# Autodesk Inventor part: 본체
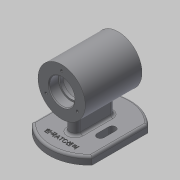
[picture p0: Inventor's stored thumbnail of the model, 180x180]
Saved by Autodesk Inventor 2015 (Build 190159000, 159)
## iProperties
Created: 2022-02
Part Number: 본체
Material: 일반
Document SubType Name: Modeling
Designer: 학생용
Density: 1 g/cm^3
Appearance: 기본값
Author: 학생용
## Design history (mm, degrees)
sketch "스케치1"
  geometry: C1 r 30 at (0, 0); 1 further point
  constraints: 1 centre point, 1 coincident
  dimensions: "d0" = 60 diameter of C1
extrude "돌출1" new body sketch "스케치1" distance "d1" = 72; taper "d2" = 0 deg
sketch "스케치2"
  geometry: C1 r 16 at (0, 0); 1 further point
  constraints: 1 centre point, 1 coincident
  dimensions: "d3" = 32 diameter of C1
extrude "돌출2" cut sketch "스케치2" distance "d4" = 12; taper "d5" = 0 deg
sketch "스케치3"
  geometry: C1 r 14 at (0, 0); 1 further point
  constraints: 1 centre point, 1 coincident
  dimensions: "d6" = 28 diameter of C1
extrude "돌출3" cut sketch "스케치3" distance "d7" = 4; taper "d8" = 0 deg
sketch "스케치4"
  geometry: C1 r 25 at (0, 0); 1 further point
  constraints: 1 centre point, 1 coincident
  dimensions: "d9" = 50 diameter of C1
extrude "돌출4" cut sketch "스케치4" distance "d10" = 40; taper "d11" = 0 deg
sketch "스케치5"
  geometry: C1 r 16 at (0, 0); 1 further point
  constraints: 1 centre point, 1 coincident
  dimensions: "d12" = 32 diameter of C1
extrude "돌출5" cut sketch "스케치5" distance "d13" = 12; taper "d14" = 0 deg
sketch "스케치6"
  geometry: C1 r 14 at (0, 0); 1 further point
  constraints: 1 centre point, 1 coincident
  dimensions: "d15" = 28 diameter of C1
extrude "돌출6" cut sketch "스케치6" distance "d16" = 4; taper "d17" = 0 deg
chamfer "모따기1" distance "d18" = 1; stored, may be unused: second distance "d19" = 2, angle "d20" = 45 deg
fillet "모깎기1" dims "d21" = 3
fillet "모깎기2" dims "d22" = 0.3
sketch "스케치7" dims "d23" = 46
  geometry: L1 (0, 0)-(0, 23.246); 2 further points
  constraints: 2 end point, 1 coincident, 1 point on line, 1 vertical, 1 vertical alignment, 2 other
hole "구멍1" sketch "스케치7" at (0, 23) diameter "d24" = 3.242; stored, may be unused: countersink angle "d28" = 90 deg, drill point angle "d30" = 118 deg; dims "d25" = 8, "d26" = 4, "d27" = 2, "d29" = 10
sketch "스케치8" dims "d34" = 46
  geometry: L1 (0, 0)-(0, -23); C1 r 1.621 at (0, -23) reference; 2 further points
  constraints: 2 coincident, 2 end point, 1 vertical, 1 vertical alignment, 2 other
hole "구멍2" sketch "스케치8" at (0, -23) diameter "d35" = 3.242; stored, may be unused: countersink angle "d39" = 90 deg, drill point angle "d41" = 118 deg; dims "d36" = 8, "d37" = 4, "d38" = 2, "d40" = 10
node "작업 평면1"
sketch "스케치9"
  geometry: L1 (-30, 0)-(30, 0) reference; L2 (30, 72)-(-30, 72) reference; L3 (-31.853, 36)-(31.853, 36); L4 (-31.85, -5.104)-(31.85, -5.104); L5 (38, 0.504)-(38, 71.496); L6 (31.85, 77.104)-(-31.85, 77.104); L7 (-38, 71.496)-(-38, 0.504); L8 (-35.299, -2.183)-(38, 77.104); L9 (44.15, -5.104)-(-37.791, 71.184); L10 (0, 0)-(0, 72); A1 r 52 centre (0, 36) between (-38, 0.504) and (38, 0.504); A2 r 52 centre (0, 36) between (38, 71.496) and (-38, 71.496)
  constraints: 16 end point, 9 point on circle, 2 centre point, 2 horizontal, 2 midpoint, 2 parallel, 2 point on line, 1 perpendicular, 1 vertical alignment
  dimensions: "d47" = 36 distance between parallel lines of L2 L3; "d50" = 52 radius of A2; "d51" = 52 radius of A1; "d52" = 76 distance between parallel lines of L5 L7; "d53" = 38 distance between parallel lines of L10 L7
extrude "돌출7" join sketch "스케치9" distance "d54" = 10; taper "d55" = 0 deg
sketch "스케치10"
  geometry: L1 (0, 17)-(0, 55); L2 (7, 17)-(7, 55); L3 (-7, 55)-(-7, 17); L4 (30, 72)-(-30, 72) reference; A1 r 7 centre (0, 17) between (-7, 17) and (7, 17); A2 r 7 centre (0, 55) between (7, 55) and (-7, 55); 2 further points
  constraints: 8 end point, 4 point on circle, 4 tangent, 2 centre point, 1 midpoint, 1 parallel, 1 vertical
  dimensions: "d56" = 14 distance between parallel lines of L2 L3; "d57" = 38 distance of L1.end L1.start; "d58" = 36 distance of point (0, 36) point (0, 0); "d59" = 36 distance from line of L4 point (0, 36)
extrude "돌출8" join sketch "스케치10" stored distance "d60" = 10; taper "d61" = 0 deg
sketch "스케치11"
  geometry: L1 (-18.165, 28.5)-(-18.165, 43.5); L2 (-13.665, 28.5)-(-13.665, 43.5); L3 (-22.665, 43.5)-(-22.665, 28.5); L4 (-30, 0)-(30, 0) reference; L5 (30, 72)-(-30, 72) reference; L6 (-18.165, 36)-(20.73, 36); L7 (0, 0)-(0, 72); L8 (20.73, 28.5)-(20.73, 43.5); L9 (16.23, 28.5)-(16.23, 43.5); L10 (25.23, 43.5)-(25.23, 28.5); A1 r 4.5 centre (-18.165, 28.5) between (-22.665, 28.5) and (-13.665, 28.5); A2 r 4.5 centre (-18.165, 43.5) between (-13.665, 43.5) and (-22.665, 43.5); A3 r 4.5 centre (20.73, 28.5) between (16.23, 28.5) and (25.23, 28.5); A4 r 4.5 centre (20.73, 43.5) between (25.23, 43.5) and (16.23, 43.5); 1 further point
  constraints: 20 end point, 8 point on circle, 8 tangent, 4 centre point, 3 midpoint, 2 parallel, 2 vertical, 1 coincident
  dimensions: "d62" = 9 distance between parallel lines of L2 L3; "d64" = 15 distance of L1.end L1.start; "d66" = 36 vertical distance of L6.start L7.start; "d68" = 36 vertical distance of L6.end L7.start; "d69" = 9 distance between parallel lines of L10 L9; "d70" = 15 distance of L8.end L8.start
extrude "돌출9" cut sketch "스케치11" stored distance "d71" = 10; taper "d72" = 0 deg
node "작업 평면2"
fillet "모깎기3" dims "d74" = 3
sketch "스케치12"
  geometry: L1 (-30, 0)-(30, 0) reference; C1 r 42.5 at (0, 36); 1 further point
  constraints: 1 centre point, 1 midpoint, 1 vertical alignment, 1 other
  dimensions: "d76" = 85 diameter of C1; "d77" = 36 distance from line of C1.centre L1
extrude "돌출10" join sketch "스케치12" distance "d78" = 0.5; taper "d79" = 0 deg
node "솔리드1"
pattern_circular "원형 패턴1" dims angle "d32" = 360 deg
pattern_circular "원형 패턴2" dims angle "d43" = 360 deg
other parameters: "d45" = -62, "d46" = 104, "d73" = 0
